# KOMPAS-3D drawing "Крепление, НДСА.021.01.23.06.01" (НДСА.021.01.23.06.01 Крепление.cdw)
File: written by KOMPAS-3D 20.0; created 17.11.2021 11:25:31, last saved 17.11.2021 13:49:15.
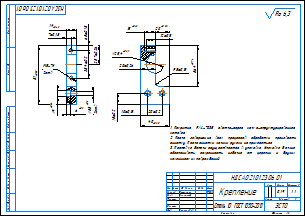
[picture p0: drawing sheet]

Sheet 1: A3, landscape

Document properties: Параметр неуказанной шероховатости: Ra 6,3; PLM_CDWXDTO: <item xmlns="http://appius.ru/pdm" xmlns:xs="http://www.w3.org/2001/XMLSchema" xmlns:xsi="http://www.w3.org/2001/XMLSchema-instance" xsi:type="item">  <element xmlns:d2p1="http://v8.1c.ru/8.1/data/enterprise/current-config" xsi:type="d2p1:CatalogRef.aps_Элемен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; Масса: 0.192777; PDM_DOCXDTO: <item xmlns="http://appius.ru/pdm" xmlns:xs="http://www.w3.org/2001/XMLSchema" xmlns:xsi="http://www.w3.org/2001/XMLSchema-instance" xsi:type="item">  <element xmlns:d2p1="http://v8.1c.ru/8.1/data/enterprise/current-config" xsi:type="d2p1:CatalogRef.aps_Элемен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; PDM_ITEMXDTO: <item xmlns="http://appius.ru/pdm" xmlns:xs="http://www.w3.org/2001/XMLSchema" xmlns:xsi="http://www.w3.org/2001/XMLSchema-instance" xsi:type="item">  <element xmlns:d2p1="http://v8.1c.ru/8.1/data/enterprise/current-config" xsi:type="d2p1:CatalogRef.aps_Элемен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; PDM_DRAWINGXDTO: <item xmlns="http://appius.ru/pdm" xmlns:xs="http://www.w3.org/2001/XMLSchema" xmlns:xsi="http://www.w3.org/2001/XMLSchema-instance" xsi:type="item">  <element xmlns:d2p1="http://v8.1c.ru/8.1/data/enterprise/current-config" xsi:type="d2p1:CatalogRef.aps_Элемен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

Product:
- Part/product: Крепление  | designation НДСА.021.01.23.06.01
    Масса: 0.192777
    additional columns: <item xmlns="http://appius.ru/pdm" xmlns:xs="http://www.w3.org/2001/XMLSchema" x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; <item xmlns="http://appius.ru/pdm" xmlns:xs="http://www.w3.org/2001/XMLSchema" x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; <item xmlns="http://appius.ru/pdm" xmlns:xs="http://www.w3.org/2001/XMLSchema" x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
    source file: НДСА.021.01.23.06.01 Крепление.cdw

Title block, sheet 1: Наименование: Крепление; designation: НДСА.021.01.23.06.01; Материал: Сталь 10  ГОСТ 1050-2013; Масса: 0,19; Количество листов документа: 1; organisation: ЭСТО; Форматы листов документа: A3; stored path: C:\Users\s.pischagina\Desktop\PLM\НДСА.021.01.23.06.01 Крепление.cdw; Разработал: Пищагина; Проверил: Белецкий; Утвердил: Виноградов; Разработал, date: 17.11.21

Views: Вид 1, Местный разрез 1, Сзади, Проекционный вид 2
Referenced files in C:\Users\s.pischagina\Desktop\PLM\: НДСА.021.01.23.06.01 Крепление.m3d
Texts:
  Ra 6,3
  НДСА.021.01.23.06.01 Крепление
Dimensions and other numbers on the sheet: 7±0,18; 14; 6,5±0,18; 38,4±0,2; 25,7±0,26; 9; 6; 5,5; 2отв; 81; -7Н; 5; 12; 15±0,2; 20±0,26; 56,4; 10±0,18; 40; 25,4; 1:1; 1; 0,19; 17.11.21

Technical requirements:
  Покрытие RAL-7035 светло-серая мелко-структурированная
  матовая.
  После завершения всех процессов обработки произвести
  очистку. После очистки голыми руками не прикасаться.
  Поставка детали осуществляется в упаковке. Упаковка должна
  обеспечивать сохранность изделия от царапин и других
  механических повреждений.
